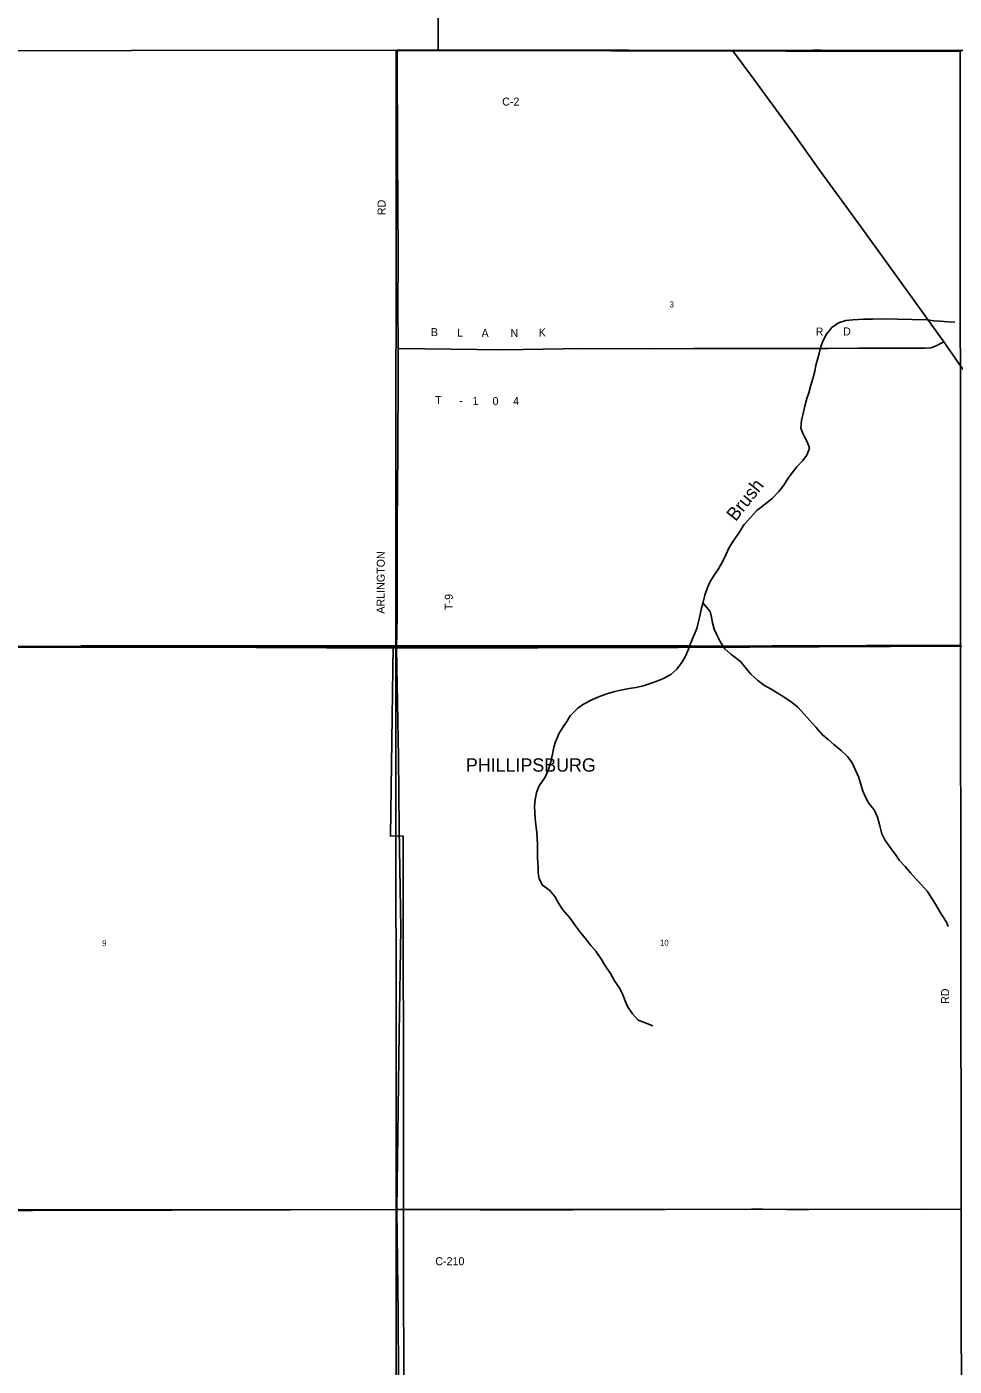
# Model space of a CAD drawing. Extents: x 1312308 to 1684953, y 460642 to 865172.
# Drawn here: x 1424442 to 1433132, y 692598 to 705151 of the extents above; entities that cross this region are included whole.
import ezdxf

# ---------------------------------------------------------------- set-up
doc = ezdxf.new("R2010")
doc.units = 0
for name, color, linetype in [('GM_X_Adjacent_County', 7, 'Continuous'), ('GM_X_Corporation_Text', 7, 'Continuous'), ('GM_X_County', 7, 'Continuous'), ('GM_X_County_Road', 7, 'Continuous'), ('GM_X_County_Road_Text', 7, 'Continuous'), ('GM_X_Minor_River', 7, 'Continuous'), ('GM_X_Minor_River_Text', 7, 'Continuous'), ('GM_X_Section', 7, 'Continuous'), ('GM_X_Section_Text', 7, 'Continuous'), ('GM_X_State_Route', 7, 'Continuous'), ('GM_X_Township', 7, 'Continuous'), ('GM_X_Township_Road', 7, 'Continuous'), ('GM_X_Township_Road_Text', 7, 'Continuous')]:
    doc.layers.add(name, color=color, linetype=linetype)

msp = doc.modelspace()

# ---------------------------------------------------------------- linework, layer by layer
at = {"layer": 'GM_X_Adjacent_County'}
for points in [[(1428350, 715531), (1428311, 710253), (1428293, 707700), (1428298, 704930), (1427914, 704930), (1422931, 704924), (1422567, 704922), (1417594, 704907), (1417259, 704901), (1416929, 704900), (1415559, 704898), (1415362, 704895), (1414978, 704894), (1414427, 704892), (1414347, 704892), (1412338, 704883), (1411570, 704882), (1409054, 704885), (1407617, 704887), (1406282, 704886), (1403774, 704892), (1403648, 704894), (1395370, 704926)], [(1428293, 707700), (1428298, 704930), (1428714, 704931), (1429302, 704927), (1431058, 704927), (1431808, 704930), (1431882, 704930), (1432293, 704927), (1432761, 704927), (1434072, 704926)]]:
    msp.add_lwpolyline(points, dxfattribs=at)
at = {"layer": 'GM_X_County'}
msp.add_lwpolyline([(1422931, 704924), (1427914, 704930), (1428298, 704930), (1428714, 704931), (1429302, 704927), (1431058, 704927), (1431808, 704930), (1431882, 704930), (1432293, 704927), (1432761, 704927), (1434072, 704926)], dxfattribs=at)
at = {"layer": 'GM_X_County_Road'}
for points in [[(1417594, 704907), (1422567, 704922), (1422931, 704924), (1427914, 704930), (1427932, 704930)], [(1427932, 704930), (1428299, 704931)], [(1428299, 704931), (1428467, 704932), (1428644, 704932), (1429130, 704932), (1429645, 704931), (1430082, 704931), (1430433, 704929), (1430744, 704929), (1431054, 704928)], [(1431054, 704928), (1431059, 704928), (1431614, 704929), (1432322, 704928), (1433389, 704929)], [(1412783, 699343), (1413310, 699341), (1414029, 699340), (1415239, 699333), (1415913, 699334), (1416768, 699332), (1417278, 699333), (1417538, 699331), (1418365, 699332), (1419226, 699334), (1420591, 699330), (1421224, 699331), (1422553, 699335), (1423343, 699336), (1424903, 699338), (1425917, 699336), (1426595, 699335), (1427908, 699327), (1429232, 699330), (1430547, 699335), (1431216, 699338), (1431868, 699340), (1433205, 699345)], [(1427870, 685497), (1427876, 685716), (1427897, 687373), (1427900, 687899), (1427912, 688658), (1427931, 691343), (1427921, 693087), (1427910, 694067), (1427931, 695719), (1427946, 696700), (1427933, 697642), (1427924, 698302), (1427908, 699327)], [(1423720, 694053), (1424497, 694059), (1424666, 694060), (1425102, 694062), (1425370, 694060), (1425477, 694062), (1425806, 694062), (1426909, 694065), (1427910, 694067), (1428694, 694064), (1429562, 694064), (1429970, 694066), (1430428, 694068), (1431232, 694069), (1431338, 694069), (1431562, 694068), (1431770, 694067), (1432838, 694069), (1433199, 694068)]]:
    msp.add_lwpolyline(points, dxfattribs=at)
at = {"layer": 'GM_X_Minor_River'}
for points in [[(1433137, 702381), (1433073, 702387), (1433005, 702392), (1432940, 702396), (1432880, 702404), (1432460, 702414), (1432368, 702411), (1432287, 702411), (1432233, 702408), (1432182, 702405), (1432118, 702399), (1432047, 702375), (1431987, 702332), (1431936, 702271), (1431906, 702212), (1431884, 702154), (1431867, 702088), (1431853, 702032), (1431837, 701975), (1431828, 701923), (1431810, 701863), (1431789, 701791), (1431771, 701721), (1431751, 701666), (1431733, 701594), (1431713, 701514), (1431702, 701462), (1431696, 701388), (1431716, 701333), (1431759, 701256), (1431777, 701201), (1431750, 701136), (1431710, 701083), (1431658, 701026), (1431615, 700971), (1431577, 700920), (1431535, 700854), (1431489, 700795), (1431423, 700727), (1431351, 700670), (1431282, 700616), (1431224, 700551), (1431164, 700485), (1431111, 700402), (1431067, 700339), (1431023, 700271), (1430991, 700202), (1430966, 700150), (1430924, 700071), (1430884, 700010), (1430842, 699947), (1430818, 699887)], [(1430818, 699887), (1430795, 699824), (1430779, 699760), (1430761, 699690), (1430749, 699626), (1430734, 699564), (1430720, 699511), (1430660, 699372), (1430643, 699318), (1430619, 699258), (1430588, 699201), (1430534, 699130), (1430478, 699081), (1430409, 699043), (1430346, 699018), (1430293, 698998), (1430218, 698974), (1430153, 698959), (1430088, 698949), (1430008, 698935), (1429951, 698922), (1429878, 698900), (1429809, 698876), (1429744, 698845), (1429658, 698803), (1429605, 698764), (1429535, 698692), (1429503, 698639), (1429463, 698581), (1429430, 698530), (1429396, 698451), (1429380, 698399), (1429369, 698335), (1429353, 698263), (1429331, 698191), (1429301, 698120), (1429242, 698037), (1429217, 697974), (1429205, 697906), (1429201, 697846), (1429202, 697789), (1429206, 697731), (1429213, 697671), (1429221, 697600), (1429226, 697548), (1429228, 697484), (1429229, 697426), (1429229, 697359), (1429233, 697275), (1429234, 697223), (1429244, 697166), (1429275, 697107), (1429340, 697061), (1429389, 697000), (1429425, 696939), (1429466, 696876), (1429532, 696800), (1429585, 696726), (1429632, 696663), (1429686, 696593), (1429727, 696542), (1429774, 696487), (1429828, 696409), (1429859, 696358), (1429913, 696280), (1429950, 696209), (1429998, 696138), (1430027, 696079), (1430048, 696024), (1430072, 695969), (1430117, 695900), (1430172, 695840), (1430237, 695815), (1430309, 695789)], [(1430777, 699751), (1430845, 699672), (1430859, 699618), (1430867, 699565), (1430883, 699504), (1430907, 699451), (1430943, 699383), (1430983, 699322), (1431039, 699271), (1431131, 699204), (1431183, 699137), (1431227, 699083), (1431291, 699023), (1431354, 698976), (1431417, 698942), (1431474, 698909), (1431538, 698867), (1431607, 698822), (1431668, 698776), (1431725, 698709), (1431781, 698649), (1431837, 698586), (1431897, 698514), (1431950, 698470), (1432006, 698425), (1432072, 698369), (1432131, 698312), (1432175, 698252), (1432208, 698185), (1432240, 698115), (1432261, 698040), (1432277, 697987), (1432305, 697924), (1432335, 697869), (1432381, 697811), (1432414, 697743), (1432437, 697662), (1432453, 697589), (1432483, 697532), (1432532, 697458), (1432582, 697393), (1432618, 697342), (1432672, 697282), (1432724, 697223), (1432774, 697167), (1432830, 697107), (1432878, 697051), (1432920, 696989), (1432956, 696927), (1432996, 696864), (1433026, 696812), (1433060, 696761), (1433075, 696720)], [(1430653, 699348), (1424950, 699353)], [(1427874, 699350), (1427850, 697568), (1427969, 697565), (1427976, 691431), (1427853, 691418), (1427832, 689060)]]:
    msp.add_lwpolyline(points, dxfattribs=at)
at = {"layer": 'GM_X_Section'}
for points in [[(1427902, 704928), (1428287, 704928), (1433188, 704919), (1433191, 699355), (1427901, 699336)], [(1422567, 699349), (1427901, 699336), (1427905, 694068), (1422559, 694065)], [(1427901, 699336), (1433191, 699355), (1433199, 694069), (1427905, 694068)], [(1422559, 694065), (1427905, 694068), (1427903, 688640), (1422564, 688632)], [(1427905, 694068), (1433199, 694069), (1433203, 688647), (1427903, 688640)]]:
    msp.add_lwpolyline(points, close=True, dxfattribs=at)
at = {"layer": 'GM_X_State_Route'}
msp.add_lwpolyline([(1434145, 700657), (1434052, 700786), (1433613, 701389), (1433542, 701494), (1433177, 701996), (1433035, 702198), (1432697, 702668), (1432261, 703272), (1431881, 703794), (1431635, 704138), (1431254, 704661), (1431054, 704928)], dxfattribs=at)
at = {"layer": 'GM_X_Township'}
msp.add_lwpolyline([(1422931, 704924), (1427914, 704930), (1428298, 704930), (1428714, 704931), (1429302, 704927), (1431058, 704927), (1431808, 704930), (1431882, 704930), (1432293, 704927), (1432761, 704927), (1434072, 704926)], dxfattribs=at)
at = {"layer": 'GM_X_Township_Road'}
for points in [[(1427908, 699327), (1427912, 699626), (1427914, 699932), (1427912, 700492), (1427919, 701165), (1427922, 701903), (1427922, 702135), (1427920, 702541), (1427921, 702972), (1427919, 703520), (1427917, 703909), (1427914, 704930)], [(1427922, 702135), (1428906, 702124), (1429657, 702135), (1430267, 702133), (1430689, 702135), (1431951, 702137), (1432235, 702139), (1432567, 702138), (1432861, 702139), (1432913, 702142), (1432958, 702157), (1433035, 702198)]]:
    msp.add_lwpolyline(points, dxfattribs=at)

# ---------------------------------------------------------------- texts
at = {"layer": 'GM_X_Corporation_Text'}
msp.add_text('PHILLIPSBURG', height=125, rotation=0, dxfattribs=at).set_placement((1428557, 698170))
at = {"layer": 'GM_X_County_Road_Text'}
for s, rotation, p in [('C-2', 359.9624, (1428897, 704412)), ('RD', 90, (1433084, 695993)), ('C-210', 359.999, (1428270, 693545))]:
    msp.add_text(s, height=75, rotation=rotation, dxfattribs=at).set_placement(p)
at = {"layer": 'GM_X_Minor_River_Text'}
msp.add_text('Brush', height=125, rotation=51.5888, dxfattribs=at).set_placement((1431085, 700509))
at = {"layer": 'GM_X_Section_Text'}
for s, p in [('3', (1430465, 702521)), ('9', (1425148, 696535)), ('10', (1430375, 696539))]:
    msp.add_text(s, height=55.3, rotation=0, dxfattribs=at).set_placement(p)
at = {"layer": 'GM_X_Township_Road_Text'}
for s, rotation, p in [('RD', 90, (1427804, 703385)), ('B', 358.8915, (1428228, 702252)), ('L', 358.934, (1428475, 702248)), ('A', 359.7146, (1428703, 702243)), ('N', 0.9491, (1428975, 702242)), ('K', 1.2534, (1429240, 702247)), ('R', 0.0976, (1431834, 702257)), ('D', 2.3145, (1432093, 702257)), ('T', 358.8128, (1428268, 701615)), ('1', 359.258, (1428618, 701608)), ('0', 359.9867, (1428807, 701605)), ('4', 1.5169, (1429000, 701605)), ('-', 358.9082, (1428493, 701610)), ('ARLINGTON', 89.7649, (1427795, 699650)), ('T-9', 90, (1428434, 699685))]:
    msp.add_text(s, height=75, rotation=rotation, dxfattribs=at).set_placement(p)

doc.saveas('drawing.dxf')
